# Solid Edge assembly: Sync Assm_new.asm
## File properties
Author: Sarvanan
Template: sync iso assembly.asm
Last saved by: CADCIM
Revision: 19
Application: Solid Edge
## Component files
casting_new.par
Brasses.par
Bolt.par
Nut.par
Lock Nut.par
Bolt_mir.par
Nut_mir.par
Lock Nut_mir.par
cap.par
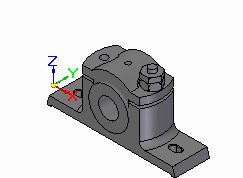
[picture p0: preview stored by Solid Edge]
